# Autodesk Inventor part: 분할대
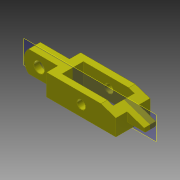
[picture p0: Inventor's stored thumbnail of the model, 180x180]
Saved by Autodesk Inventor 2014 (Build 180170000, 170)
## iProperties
Created: 2016-11
Part Number: 분할대
Material: 강철, 연강
Document SubType Name: Modeling
Designer: mduedu
Density: 1 g/cm^3
Appearance: 노란색
Author: mduedu
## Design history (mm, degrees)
sketch "스케치1"
  geometry: L1 (32.5, 16)-(-32.5, 16); L2 (-32.5, 16)-(-32.5, -16); L3 (-32.5, -16)-(32.5, -16); L4 (32.5, -16)-(32.5, 16); L5 (24, 10)-(-24, 10); L6 (-24, 10)-(-24, -10); L7 (-24, -10)-(24, -10); L8 (24, -10)-(24, 10); L9 (24, 0)-(-24, 0); L10 (0, -16)-(0, 16); 4 further points
  constraints: 20 end point, 7 midpoint, 4 parallel, 2 coincident, 2 horizontal, 2 perpendicular, 1 horizontal alignment
  dimensions: "d0" = 20 distance of L5.end L6.end; "d2" = 32 distance between parallel lines of L1 L3; "d3" = 48 distance of L5.start L5.end; "d4" = 65 distance of L1.start L1.end
extrude "돌출1" new body sketch "스케치1" distance "d5" = 20; taper "d6" = 0 deg
sketch "스케치2"
  geometry: L1 (0, 0)-(65, 0) reference; L2 (65, 0)-(65, 20) reference; L3 (0, 20)-(65, 20) reference; L4 (0, 0)-(0, 20) reference; L5 (32.5, 0)-(32.5, 20); C1 r 4 at (32.5, 10)
  constraints: 2 end point, 2 midpoint, 1 centre point
  dimensions: "d7" = 8 diameter of C1
extrude "돌출2" cut sketch "스케치2" stored distance "d8" = 20; taper "d9" = 0 deg
chamfer "모따기1" distance "d10" = 0.2; stored, may be unused: second distance "d11" = 2, angle "d12" = 45 deg
sketch "스케치3"
  geometry: L1 (-32.5, 0)-(-32.5, 20) reference; L2 (-32.5, 20)-(-59.798, 20); L3 (-64, 20)-(-64, 0); L4 (-64, 0)-(-59.798, 0); L5 (-32.5, 0)-(-32.5, 20); L6 (-59.798, 20)-(-64, 20); L7 (-59.798, 0)-(-32.5, 0); C1 r 4.2 at (0, 10) reference; C2 r 5 at (-50, 10); A1 r 14 centre (-50, 10) between (-59.798, 20) and (-59.798, 0); 1 further point
  constraints: 12 end point, 5 parallel, 2 centre point, 2 horizontal, 2 perpendicular, 2 point on circle, 1 coincident, 1 horizontal alignment, 1 tangent
  dimensions: "d13" = 64 distance from line of L3 C1.centre; "d14" = 14 radius of A1; "d15" = 10 diameter of C2
extrude "돌출3" join sketch "스케치3" stored distance "d16" = 11; taper "d17" = 0 deg
sketch "스케치4"
  geometry: L1 (32.5, 0)-(32.5, 20) reference; L2 (32.5, 20)-(48.5, 20); L3 (48.5, 20)-(48.5, 6); L4 (48.5, 6)-(32.5, 6); L5 (32.5, 6)-(32.5, 20); L6 (32.5, 0)-(-32.5, 0) reference; 1 further point
  constraints: 8 end point, 2 parallel, 1 horizontal, 1 perpendicular
  dimensions: "d18" = 16 distance of L1.end L2.end; "d19" = 6 distance between parallel lines of L4 L6
extrude "돌출4" join sketch "스케치4" stored distance "d20" = 11; taper "d21" = 0 deg
chamfer "모따기2" distance "d22" = 30; stored, may be unused: second distance "d23" = 10, angle "d24" = 45 deg
chamfer "모따기3" distance "d25" = 1; stored, may be unused: second distance "d26" = 10, angle "d27" = 45 deg
chamfer "모따기4" distance "d28" = 0.2; stored, may be unused: second distance "d29" = 10, angle "d30" = 45 deg
node "작업 평면1"
node "솔리드1"
node "투영된 루프1"
